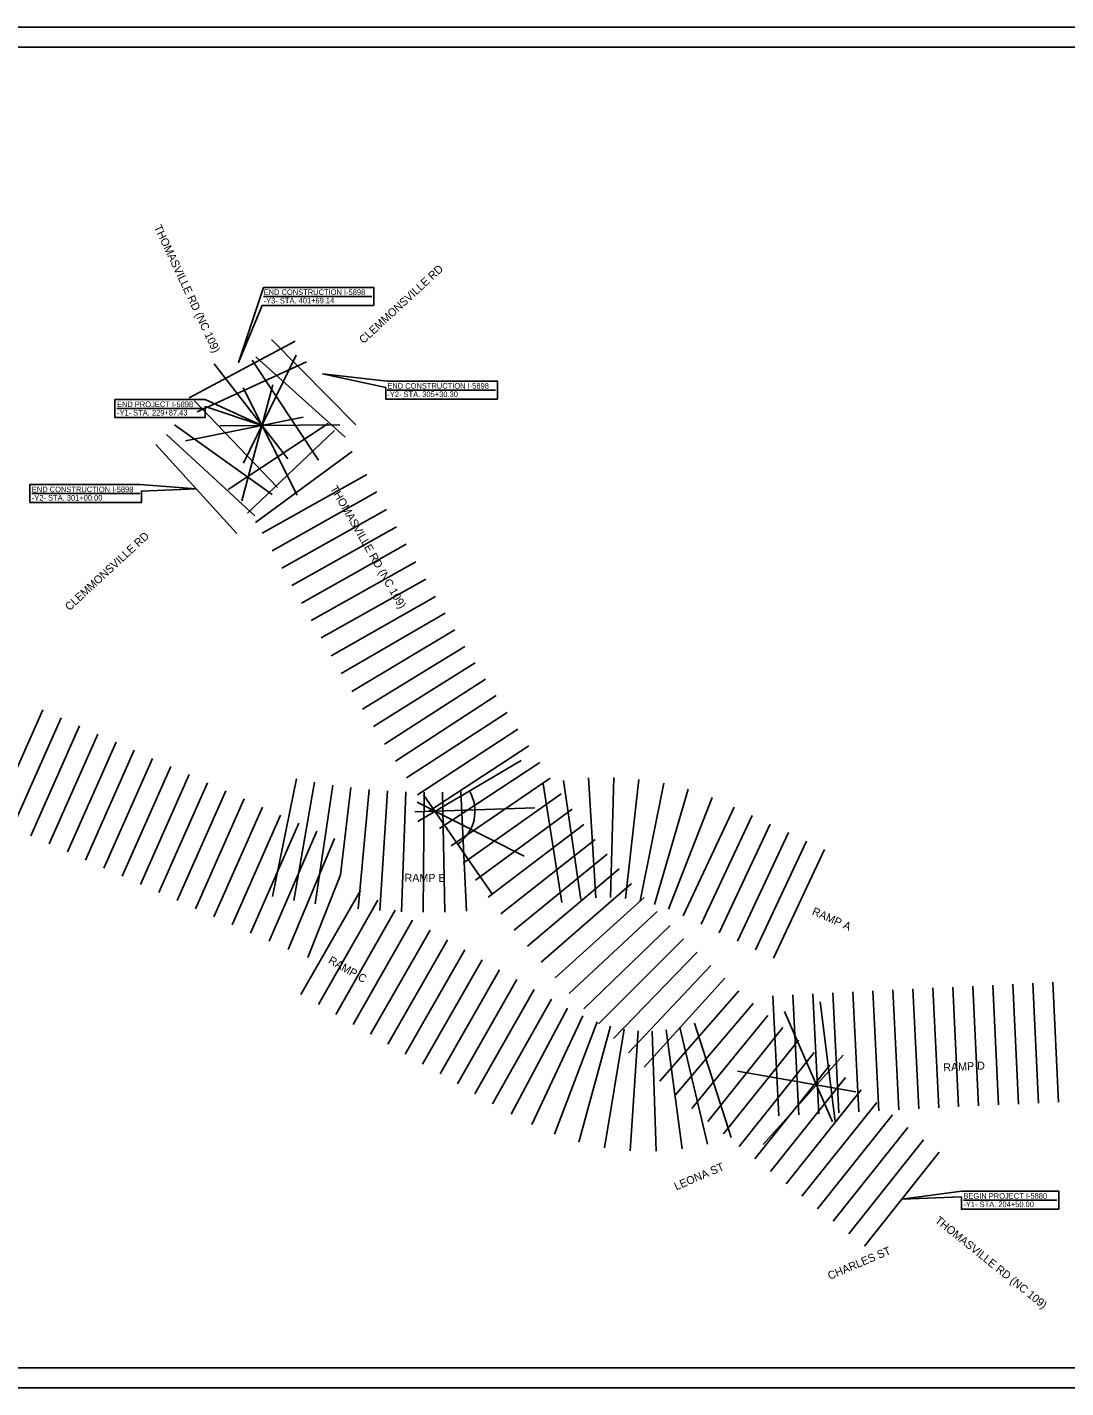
# Model space of a CAD drawing. Extents: x 1637454 to 1644154, y 841334 to 844734.
# Drawn here: x 1639782 to 1642378, y 841334 to 844734 of the extents above; entities that cross this region are included whole.
import ezdxf

# ---------------------------------------------------------------- set-up
doc = ezdxf.new("R2010")
doc.units = 0
for name, color, linetype in [('Exist Roads EOT Text', 7, 'Continuous'), ('Prop Conc 2ft 6in Curb and Gutter', 7, 'Continuous'), ('Prop Shear Point Element on Plans', 7, 'Continuous'), ('Scratch_Level_1', 7, 'Continuous'), ('Sheet Plan And Profile CELL', 7, 'Continuous')]:
    doc.layers.add(name, color=color, linetype=linetype)

msp = doc.modelspace()

# ---------------------------------------------------------------- linework, layer by layer
at = {"layer": 'Prop Conc 2ft 6in Curb and Gutter'}
for p, q in [((1640373.3, 844061.2), (1640643.4, 844061.2)), ((1640682.3, 843827.2), (1640952.4, 843827.2)), ((1640006.7, 843781.1), (1640222.2, 843781.1)), ((1639794, 843568.5), (1640064.2, 843568.5)), ((1642121.8, 841802.9), (1642355, 841802.9))]:
    msp.add_line(p, q, dxfattribs=at)
for points in [[(1640648.4, 844038.6), (1640648.4, 844083.7), (1640373.3, 844083.7), (1640310.6, 843895.7), (1640369.5, 844038.6), (1640369.5, 844038.6)], [(1640957.4, 843804.6), (1640957.4, 843849.7), (1640682.3, 843849.7), (1640520.7, 843867.5), (1640678.5, 843833.5), (1640678.5, 843804.6)], [(1640001.7, 843758.5), (1640001.7, 843803.6), (1640227.2, 843803.6), (1640369, 843738.6), (1640227.2, 843786.1), (1640227.2, 843758.5)], [(1639789, 843546), (1639789, 843591), (1640064.2, 843591), (1640204.9, 843580), (1640068, 843574.9), (1640068, 843546)], [(1642360, 841780.3), (1642360, 841825.4), (1642116.8, 841825.4), (1641968.1, 841805.1), (1642116.8, 841811.3), (1642116.8, 841780.3)]]:
    msp.add_lwpolyline(points, close=True, dxfattribs=at)
at = {"layer": 'Prop Shear Point Element on Plans'}
for p, q in [((1640187.3, 843808.1), (1640451.8, 843949.6)), ((1640604, 843740.1), (1640393.3, 843953.5)), ((1640323.1, 843644.2), (1640454.2, 843914)), ((1640480.2, 843897.6), (1640207.3, 843772.8)), ((1640433.3, 843655.6), (1640249.6, 843892.8)), ((1640344.2, 843901.9), (1640510.6, 843652.3)), ((1640576.6, 843709.4), (1640353.6, 843910.1)), ((1640318.8, 843550.2), (1640396, 843840.1)), ((1640456.8, 843564.5), (1640321.7, 843832.4)), ((1640200.4, 843800.4), (1640407.7, 843583.6)), ((1640177.8, 843700), (1640471.9, 843759.4)), ((1640351, 843512.9), (1640130.7, 843716.5)), ((1640394.4, 843566.2), (1640150.4, 843740.7)), ((1640264, 843737.9), (1640564, 843740.1)), ((1640284.3, 843578.7), (1640534.8, 843743.8)), ((1640332.8, 843519.9), (1640550.6, 843726.2)), ((1640305.9, 843469.1), (1640103.9, 843690.8)), ((1640352.8, 843496), (1640594.6, 843673.5)), ((1640631.5, 843616.1), (1640369.9, 843469.3)), ((1640656, 843572.5), (1640394.4, 843425.7)), ((1640680.5, 843528.9), (1640418.8, 843382.1)), ((1640704.9, 843485.3), (1640443.3, 843338.5)), ((1640729.4, 843441.7), (1640467.8, 843294.9)), ((1640753.9, 843398.1), (1640492.2, 843251.3)), ((1640778.3, 843354.5), (1640516.7, 843207.7)), ((1640541.7, 843163.3), (1640802.4, 843311.7)), ((1640567.4, 843118.6), (1640826.6, 843269.7)), ((1640851.2, 843228), (1640593.7, 843074.2)), ((1640620.3, 843030.1), (1640876.3, 843186.6)), ((1640647.5, 842986.2), (1640901.7, 843145.4)), ((1640675.1, 842942.6), (1640927.7, 843104.5)), ((1640702.9, 842899.6), (1640954.2, 843063.6)), ((1639821.6, 843028.3), (1639700, 842754.1)), ((1639867.3, 843008.1), (1639745.7, 842733.8)), ((1640730.3, 842857.8), (1640981.5, 843021.7)), ((1639913, 842987.8), (1639791.4, 842713.5)), ((1639958.7, 842967.5), (1639837.1, 842693.3)), ((1640757.6, 842815.9), (1641008.8, 842979.8)), ((1640004.4, 842947.3), (1639882.8, 842673)), ((1640784.9, 842774), (1641036.1, 842938)), ((1640050.1, 842927), (1639928.5, 842652.7)), ((1640095.8, 842906.7), (1639974.2, 842632.5)), ((1640758.3, 842749.3), (1641016.6, 842901.9)), ((1640812.7, 842731.5), (1641063.1, 842896.8)), ((1640141.5, 842886.5), (1640019.9, 842612.2)), ((1640187.3, 842866.2), (1640065.7, 842591.9)), ((1640233, 842845.9), (1640111.4, 842571.7)), ((1640455.4, 842855.8), (1640395.7, 842561.8)), ((1640448.9, 842551.7), (1640500.5, 842847.3)), ((1640545.8, 842840), (1640502.4, 842543.2)), ((1640565.5, 842615.9), (1640591.3, 842834)), ((1640609.8, 842530.4), (1640636.9, 842829.2)), ((1640842, 842687.9), (1641089.6, 842857.4)), ((1641071.7, 842843.3), (1641118.4, 842547)), ((1641122.7, 842851.3), (1641166.3, 842554.5)), ((1641203.1, 842558.3), (1641185.2, 842857.8)), ((1641248.1, 842858.8), (1641240.2, 842558.9)), ((1641277.1, 842556.3), (1641310.9, 842854.4)), ((1641373.1, 842844.7), (1641313.8, 842550.6)), ((1641349.7, 842541.7), (1641434.1, 842829.6)), ((1640278.7, 842825.7), (1640157.1, 842551.4)), ((1640324.4, 842805.4), (1640202.8, 842531.1)), ((1640663.8, 842526.3), (1640682.7, 842825.7)), ((1640717.8, 842523.6), (1640728.5, 842823.4)), ((1640756.7, 842797.2), (1641024.6, 842662.3)), ((1640771.9, 842522.5), (1640774.4, 842822.4)), ((1640772.9, 842815.9), (1640943.4, 842569)), ((1640826.1, 842522.8), (1640820.2, 842822.7)), ((1640880.2, 842524.6), (1640866.1, 842824.2)), ((1640872, 842644.8), (1641116.7, 842818.4)), ((1641493.7, 842809.3), (1641384.8, 842529.7)), ((1640370.1, 842785.1), (1640248.5, 842510.9)), ((1640415.8, 842764.9), (1640294.2, 842490.6)), ((1640751.4, 842773.1), (1641051.2, 842783.1)), ((1640902.7, 842602.3), (1641144.5, 842779.9)), ((1641421.3, 842513.7), (1641548.8, 842785.2)), ((1641466.5, 842492.4), (1641594.1, 842764)), ((1640461.2, 842744.8), (1640340.2, 842470.2)), ((1640387, 842449.8), (1640506, 842725.2)), ((1641173, 842741.8), (1640934.2, 842560.2)), ((1641511.8, 842471.2), (1641639.3, 842742.7)), ((1640434.7, 842429.5), (1640550.4, 842706.3)), ((1640966.3, 842518.7), (1641202, 842704.3)), ((1641557, 842449.9), (1641684.6, 842721.5)), ((1641602.3, 842428.7), (1641729.8, 842700.2)), ((1641231.7, 842667.2), (1640999.1, 842477.7)), ((1641647.5, 842407.4), (1641775.1, 842678.9)), ((1641032.6, 842437.3), (1641262, 842630.6)), ((1640565.5, 842615.9), (1640483.4, 842409.6)), ((1641292.9, 842594.5), (1641066.8, 842397.4)), ((1640615.4, 842577), (1640466.6, 842316.5)), ((1641101.6, 842358.1), (1641324.4, 842559)), ((1640658.8, 842552.2), (1640510, 842291.7)), ((1640702.2, 842527.4), (1640553.5, 842266.9)), ((1641356.5, 842524), (1641137, 842319.4)), ((1640745.6, 842502.6), (1640596.9, 842242.1)), ((1641173.2, 842281.3), (1641389.2, 842489.5)), ((1640789, 842477.8), (1640640.3, 842217.3)), ((1640832.5, 842453), (1640683.7, 842192.5)), ((1641422.4, 842455.6), (1641209.9, 842243.8)), ((1640875.9, 842428.2), (1640727.1, 842167.7)), ((1641247.3, 842206.9), (1641456.2, 842422.2)), ((1640919.3, 842403.5), (1640770.6, 842142.9)), ((1641490.6, 842389.4), (1641285.2, 842170.7)), ((1640962.7, 842378.7), (1640814, 842118.1)), ((1641006.2, 842353.9), (1640857.4, 842093.3)), ((1641323.8, 842135.1), (1641525.5, 842357.2)), ((1641049.6, 842329.1), (1640900.8, 842068.6)), ((1641560.9, 842325.5), (1641363, 842100.1)), ((1641760.5, 842018.5), (1641745.6, 842318.1)), ((1641810.4, 842021), (1641795.6, 842320.6)), ((1641860.4, 842023.4), (1641845.5, 842323.1)), ((1641910.3, 842025.9), (1641895.4, 842325.5)), ((1641960.2, 842028.4), (1641945.4, 842328)), ((1642010.2, 842030.8), (1641995.3, 842330.5)), ((1642060.1, 842033.3), (1642045.3, 842333)), ((1642110, 842035.8), (1642095.2, 842335.4)), ((1642145.2, 842337.9), (1642159.9, 842038.3)), ((1642209.8, 842040.7), (1642195.2, 842340.3)), ((1642245.3, 842342.8), (1642259.6, 842043.1)), ((1642309.4, 842045.5), (1642295.3, 842345.1)), ((1642345.4, 842347.5), (1642359.3, 842047.8)), ((1640944.8, 842043.5), (1641092.4, 842304.7)), ((1640992.2, 842017.5), (1641132.7, 842282.5)), ((1641402.7, 842065.8), (1641596.9, 842294.5)), ((1641660.6, 842013.5), (1641645.8, 842313.2)), ((1641710.5, 842016), (1641695.7, 842315.6)), ((1641801.8, 842000.4), (1641763.8, 842298)), ((1641170.6, 842263.5), (1641043.6, 841991.7)), ((1641100, 841967.8), (1641206.3, 842248.3)), ((1641633.3, 842264), (1641443, 842032.1)), ((1641794.5, 841998.9), (1641674.7, 842273.9)), ((1641161.2, 841947.8), (1641240.1, 842237.3)), ((1641224.7, 841933.9), (1641274.3, 842229.8)), ((1641289.2, 841926.4), (1641309, 842225.7)), ((1641354.2, 841925.3), (1641344, 842225.1)), ((1641418.9, 841930.8), (1641378.9, 842228.1)), ((1641482.8, 841942.7), (1641413.3, 842234.5)), ((1641541.9, 841959.6), (1641450.2, 842245.3)), ((1641483.6, 841999.4), (1641670.6, 842234)), ((1641522.7, 841968.2), (1641709.7, 842202.8)), ((1641561.8, 841937.1), (1641748.8, 842171.7)), ((1641821.3, 842165), (1641621.1, 841941.6)), ((1641853.1, 842073.3), (1641557.6, 842125.2)), ((1641600.9, 841905.9), (1641787.9, 842140.5)), ((1641640, 841874.7), (1641827, 842109.3)), ((1641679.1, 841843.6), (1641866.1, 842078.2)), ((1641718.2, 841812.4), (1641905.2, 842047)), ((1641757.3, 841781.3), (1641944.3, 842015.9)), ((1641796.4, 841750.1), (1641983.4, 841984.7)), ((1641835.5, 841718.9), (1642022.5, 841953.5)), ((1641874.6, 841687.8), (1642061.6, 841922.4))]:
    msp.add_line(p, q, dxfattribs=at)
msp.add_arc((1640801.3, 842774.8), 100, 304.6259, 30.5695, dxfattribs=at)
at = {"layer": 'Scratch_Level_1'}
msp.add_lwpolyline([(1637454.2, 841333.9), (1637454.2, 844733.9), (1644154.2, 844733.9), (1644154.2, 841333.9)], close=True, dxfattribs=at)
at = {"layer": 'Sheet Plan And Profile CELL'}
msp.add_lwpolyline([(1637504.2, 841383.9), (1637504.2, 844683.9), (1644104.2, 844683.9), (1644104.2, 841383.9)], close=True, dxfattribs=at)

# ---------------------------------------------------------------- texts
at = {"layer": 'Exist Roads EOT Text'}
for s, rotation, p in [('THOMASVILLE RD (NC 109)', 295.1635, (1640098.8, 844234.3)), ('CLEMMONSVILLE RD', 42.7382, (1640622.9, 843941.8)), ('THOMASVILLE RD (NC 109)', 299.9185, (1640538.9, 843581.6)), ('CLEMMONSVILLE RD', 42.7382, (1639888.1, 843274.4)), ('RAMP B', 359.7341, (1640725.3, 842598.4)), ('RAMP A', 335.9166, (1641741.9, 842517.5)), ('RAMP C', 330.2753, (1640533.1, 842396.6)), ('RAMP D', 2.8284, (1642072.1, 842124.3)), ('LEONA ST', 23.1321, (1641404.2, 841827)), ('THOMASVILLE RD (NC 109)', 321.1266, (1642049, 841749.2)), ('CHARLES ST', 23.1321, (1641788, 841603.4))]:
    msp.add_text(s, height=20, rotation=rotation, dxfattribs=at).set_placement(p)
at = {"layer": 'Prop Conc 2ft 6in Curb and Gutter'}
for s, p in [('-Y3- STA. 401+69.14', (1640373.3, 844043.7)), ('END CONSTRUCTION I-5898', (1640373.3, 844064.7)), ('-Y2- STA. 305+30.30', (1640682.3, 843809.7)), ('END CONSTRUCTION I-5898', (1640682.3, 843830.7)), ('END PROJECT I-5898', (1640006.7, 843784.6)), ('-Y1- STA. 229+87.43', (1640006.7, 843763.6)), ('END CONSTRUCTION I-5898', (1639794, 843572)), ('-Y2- STA. 301+00.00', (1639794, 843551)), ('BEGIN PROJECT I-5880', (1642121.8, 841806.4)), ('-Y1- STA. 204+50.00', (1642121.8, 841785.4))]:
    msp.add_text(s, height=14, rotation=360, dxfattribs=at).set_placement(p)

doc.saveas('drawing.dxf')
